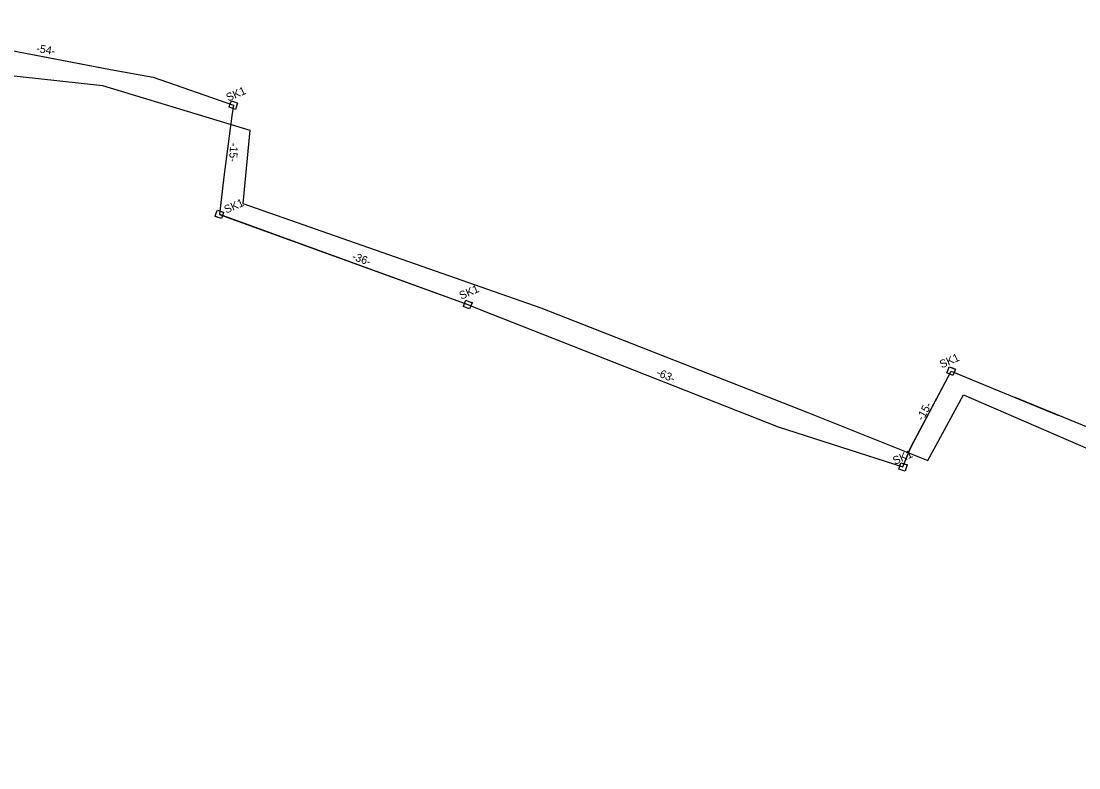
# Model space of a CAD drawing. Extents: x 6494530 to 6506885, y 5884901 to 5892312.
# Drawn here: x 6499332.9 to 6499475, y 5887627.2 to 5887727.6 of the extents above; entities that cross this region are included whole.
import ezdxf

# ---------------------------------------------------------------- set-up
doc = ezdxf.new("R2010")
doc.units = 0
for name, color, linetype in [('kabel W KANALIZACJI ISTN', 7, 'Continuous'), ('studnie do wyrysu', 7, 'Continuous'), ('trasa kanalizacji do wyrysu', 7, 'Continuous')]:
    doc.layers.add(name, color=color, linetype=linetype)

# ---------------------------------------------------------------- blocks, each defined once
blk = doc.blocks.new('ELARM2_27')
at = {"layer": 'studnie do wyrysu'}
blk.add_lwpolyline([(0, 0.45), (0.45, 0.45), (0.45, 0), (0.45, -0.45), (0, -0.45), (-0.45, -0.45), (-0.45, 0), (-0.45, 0.45)], close=True, dxfattribs=at)

msp = doc.modelspace()

# ---------------------------------------------------------------- linework, layer by layer
at = {"layer": 'kabel W KANALIZACJI ISTN'}
msp.add_lwpolyline([(6499307.31, 5887722.96), (6499343.79, 5887718.98), (6499363.61, 5887712.96), (6499362.68, 5887703.08), (6499402.72, 5887689.06), (6499438.59, 5887674.99), (6499454.69, 5887668.52), (6499459.49, 5887677.36), (6499509.73, 5887655.58), (6499508.58, 5887649.79), (6499539.76, 5887634.33), (6499552.17, 5887627.21)], dxfattribs=at)
at = {"layer": 'trasa kanalizacji do wyrysu'}
for points in [[(6499200, 5887702.73), (6499205.18, 5887704.15), (6499213.96, 5887706.58), (6499217.63, 5887707.07), (6499232.22, 5887710.84), (6499234.72, 5887711.24), (6499251.25, 5887715.34), (6499258.34, 5887717.61), (6499260.66, 5887718.13), (6499264.13, 5887717.94), (6499286.93, 5887723.59), (6499301.68, 5887727.63), (6499309.68, 5887726.99), (6499320.39, 5887725.83), (6499344.18, 5887721.25)], [(6499200, 5887702.73), (6499205.18, 5887704.15), (6499213.96, 5887706.58), (6499217.63, 5887707.07), (6499232.22, 5887710.84), (6499234.72, 5887711.24), (6499251.25, 5887715.34), (6499258.34, 5887717.61), (6499260.66, 5887718.13), (6499264.13, 5887717.94), (6499286.93, 5887723.59), (6499301.68, 5887727.63), (6499309.68, 5887726.99), (6499320.39, 5887725.83), (6499344.18, 5887721.25)], [(6499200, 5887702.73), (6499205.18, 5887704.14), (6499213.96, 5887706.57), (6499217.63, 5887707.06), (6499232.22, 5887710.83), (6499234.72, 5887711.23), (6499251.25, 5887715.33), (6499258.34, 5887717.6), (6499260.66, 5887718.12), (6499264.13, 5887717.93), (6499286.93, 5887723.58), (6499301.68, 5887727.62), (6499309.68, 5887726.98), (6499320.39, 5887725.82), (6499344.18, 5887721.25)], [(6499200, 5887702.73), (6499205.18, 5887704.14), (6499213.96, 5887706.57), (6499217.63, 5887707.06), (6499232.22, 5887710.83), (6499234.72, 5887711.23), (6499251.25, 5887715.33), (6499258.34, 5887717.6), (6499260.66, 5887718.12), (6499264.13, 5887717.93), (6499286.93, 5887723.58), (6499301.68, 5887727.62), (6499309.68, 5887726.98), (6499320.39, 5887725.82), (6499344.18, 5887721.25)], [(6499200, 5887702.73), (6499205.18, 5887704.14), (6499213.96, 5887706.57), (6499217.63, 5887707.06), (6499232.22, 5887710.83), (6499234.72, 5887711.23), (6499251.25, 5887715.33), (6499258.34, 5887717.6), (6499260.66, 5887718.12), (6499264.13, 5887717.93), (6499286.93, 5887723.58), (6499301.68, 5887727.62), (6499309.68, 5887726.98), (6499320.39, 5887725.82), (6499344.18, 5887721.25)], [(6499200, 5887702.73), (6499205.18, 5887704.14), (6499213.96, 5887706.57), (6499217.63, 5887707.06), (6499232.22, 5887710.83), (6499234.72, 5887711.23), (6499251.25, 5887715.33), (6499258.34, 5887717.6), (6499260.66, 5887718.12), (6499264.13, 5887717.93), (6499286.93, 5887723.58), (6499301.68, 5887727.62), (6499309.68, 5887726.98), (6499320.39, 5887725.82), (6499344.18, 5887721.25)], [(6499333.97, 5887723.22), (6499344.9, 5887721.12), (6499350.6, 5887720.08), (6499361.39, 5887716.34), (6499361.2, 5887714.9), (6499360.1, 5887706.68), (6499359.51, 5887701.65), (6499392.88, 5887689.51), (6499394.63, 5887688.81), (6499434.58, 5887673.09), (6499451.36, 5887667.68), (6499452.42, 5887670.32), (6499457.83, 5887680.57), (6499472.19, 5887674.66)], [(6499333.97, 5887723.22), (6499344.9, 5887721.12), (6499350.6, 5887720.08), (6499361.39, 5887716.34), (6499361.2, 5887714.9), (6499360.1, 5887706.68), (6499359.51, 5887701.65), (6499392.88, 5887689.51), (6499394.63, 5887688.81), (6499434.58, 5887673.09), (6499451.36, 5887667.68), (6499452.42, 5887670.32), (6499457.83, 5887680.57), (6499472.19, 5887674.66)], [(6499333.97, 5887723.22), (6499344.9, 5887721.12), (6499350.6, 5887720.08), (6499361.39, 5887716.34), (6499361.2, 5887714.9), (6499360.1, 5887706.68), (6499359.51, 5887701.65), (6499392.88, 5887689.51), (6499394.63, 5887688.81), (6499434.58, 5887673.09), (6499451.36, 5887667.68), (6499452.42, 5887670.32), (6499457.83, 5887680.57), (6499472.19, 5887674.66)], [(6499333.97, 5887723.22), (6499344.9, 5887721.12), (6499350.6, 5887720.08), (6499361.39, 5887716.34), (6499361.2, 5887714.9), (6499360.1, 5887706.68), (6499359.51, 5887701.65), (6499392.88, 5887689.51), (6499394.63, 5887688.81), (6499434.58, 5887673.09), (6499451.36, 5887667.68), (6499452.42, 5887670.32), (6499457.83, 5887680.57), (6499472.19, 5887674.66)], [(6499333.97, 5887723.21), (6499344.9, 5887721.11), (6499350.6, 5887720.07), (6499361.39, 5887716.33), (6499361.2, 5887714.89), (6499360.1, 5887706.67), (6499359.51, 5887701.64), (6499392.88, 5887689.5), (6499394.63, 5887688.8), (6499434.58, 5887673.08), (6499451.36, 5887667.67), (6499452.42, 5887670.31), (6499457.83, 5887680.56), (6499472.19, 5887674.65)], [(6499333.97, 5887723.21), (6499344.9, 5887721.11), (6499350.6, 5887720.07), (6499361.39, 5887716.33), (6499361.2, 5887714.89), (6499360.1, 5887706.67), (6499359.51, 5887701.64), (6499392.88, 5887689.5), (6499394.63, 5887688.8), (6499434.58, 5887673.08), (6499451.36, 5887667.67), (6499452.42, 5887670.31), (6499457.83, 5887680.56), (6499472.19, 5887674.65)], [(6499333.97, 5887723.21), (6499344.9, 5887721.11), (6499350.6, 5887720.07), (6499361.39, 5887716.33), (6499361.2, 5887714.89), (6499360.1, 5887706.67), (6499359.51, 5887701.64), (6499392.88, 5887689.5), (6499394.63, 5887688.8), (6499434.58, 5887673.08), (6499451.36, 5887667.67), (6499452.42, 5887670.31), (6499457.83, 5887680.56), (6499472.19, 5887674.65)], [(6499333.97, 5887723.21), (6499344.9, 5887721.11), (6499350.6, 5887720.07), (6499361.39, 5887716.33), (6499361.2, 5887714.89), (6499360.1, 5887706.67), (6499359.51, 5887701.64), (6499392.88, 5887689.5), (6499394.63, 5887688.8), (6499434.58, 5887673.08), (6499451.36, 5887667.67), (6499452.42, 5887670.31), (6499457.83, 5887680.56), (6499472.19, 5887674.65)], [(6499333.97, 5887723.21), (6499344.9, 5887721.11), (6499350.6, 5887720.07), (6499361.39, 5887716.33), (6499361.2, 5887714.89), (6499360.1, 5887706.67), (6499359.51, 5887701.64), (6499392.88, 5887689.5), (6499394.63, 5887688.8), (6499434.58, 5887673.08), (6499451.36, 5887667.67), (6499452.42, 5887670.31), (6499457.83, 5887680.56), (6499472.19, 5887674.65)], [(6499333.97, 5887723.21), (6499344.9, 5887721.11), (6499350.6, 5887720.07), (6499361.39, 5887716.33), (6499361.2, 5887714.89), (6499360.1, 5887706.67), (6499359.51, 5887701.64), (6499392.88, 5887689.5), (6499394.63, 5887688.8), (6499434.58, 5887673.08), (6499451.36, 5887667.67), (6499452.42, 5887670.31), (6499457.83, 5887680.56), (6499472.19, 5887674.65)], [(6499333.97, 5887723.21), (6499344.9, 5887721.11), (6499350.6, 5887720.07), (6499361.39, 5887716.33), (6499361.2, 5887714.89), (6499360.1, 5887706.67), (6499359.51, 5887701.64), (6499392.88, 5887689.5), (6499394.63, 5887688.8), (6499434.58, 5887673.08), (6499451.36, 5887667.67), (6499452.42, 5887670.31), (6499457.83, 5887680.56), (6499472.19, 5887674.65)], [(6499333.97, 5887723.21), (6499344.9, 5887721.11), (6499350.6, 5887720.07), (6499361.39, 5887716.33), (6499361.2, 5887714.89), (6499360.1, 5887706.67), (6499359.51, 5887701.64), (6499392.88, 5887689.5), (6499394.63, 5887688.8), (6499434.58, 5887673.08), (6499451.36, 5887667.67), (6499452.42, 5887670.31), (6499457.83, 5887680.56), (6499472.19, 5887674.65)], [(6499466.39, 5887677.04), (6499487.52, 5887668.35), (6499489.54, 5887665.93), (6499491.37, 5887665.2), (6499492.87, 5887665.38), (6499508.15, 5887658.35), (6499506.05, 5887650.18), (6499505.63, 5887649.07), (6499517.16, 5887642.63)], [(6499466.39, 5887677.04), (6499487.52, 5887668.34), (6499489.54, 5887665.92), (6499491.37, 5887665.19), (6499492.87, 5887665.37), (6499508.15, 5887658.34), (6499506.05, 5887650.17), (6499505.63, 5887649.06), (6499517.16, 5887642.62)], [(6499466.39, 5887677.04), (6499487.52, 5887668.34), (6499489.54, 5887665.92), (6499491.37, 5887665.19), (6499492.87, 5887665.37), (6499508.15, 5887658.34), (6499506.05, 5887650.17), (6499505.63, 5887649.06), (6499517.16, 5887642.62)], [(6499466.39, 5887677.04), (6499487.52, 5887668.34), (6499489.54, 5887665.92), (6499491.37, 5887665.19), (6499492.87, 5887665.37), (6499508.15, 5887658.34), (6499506.05, 5887650.17), (6499505.63, 5887649.06), (6499517.16, 5887642.62)], [(6499466.39, 5887677.04), (6499487.52, 5887668.34), (6499489.54, 5887665.92), (6499491.37, 5887665.19), (6499492.87, 5887665.37), (6499508.15, 5887658.34), (6499506.05, 5887650.17), (6499505.63, 5887649.06), (6499517.16, 5887642.62)], [(6499466.39, 5887677.04), (6499487.52, 5887668.35), (6499489.54, 5887665.93), (6499491.37, 5887665.2), (6499492.87, 5887665.38), (6499508.15, 5887658.35), (6499506.05, 5887650.18), (6499505.63, 5887649.07), (6499517.16, 5887642.63)]]:
    msp.add_lwpolyline(points, dxfattribs=at)

# ---------------------------------------------------------------- block references
at = {"layer": 'studnie do wyrysu'}
for p, rotation in [((6499361.39, 5887716.33), -20.10942046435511), ((6499361.39, 5887716.33), -20.10942046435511), ((6499361.39, 5887716.33), -20.10942046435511), ((6499361.39, 5887716.33), -20.10942046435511), ((6499361.39, 5887716.33), -20.10942046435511), ((6499361.39, 5887716.33), -20.10942046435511), ((6499359.51, 5887701.65), 160.10667272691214), ((6499359.51, 5887701.64), 160.10667272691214), ((6499359.51, 5887701.64), 160.10667272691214), ((6499359.51, 5887701.64), 160.10667272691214), ((6499359.51, 5887701.64), 160.10667272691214), ((6499359.51, 5887701.65), 160.10667272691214), ((6499392.88, 5887689.51), -21.240071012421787), ((6499392.88, 5887689.51), -21.240071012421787), ((6499392.88, 5887689.5), -21.240071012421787), ((6499392.88, 5887689.5), -21.240071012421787), ((6499392.88, 5887689.5), -21.240071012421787), ((6499392.88, 5887689.5), -21.240071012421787), ((6499457.83, 5887680.57), -22.59255526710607), ((6499457.83, 5887680.56), -22.59255526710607), ((6499457.83, 5887680.56), -22.59255526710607), ((6499457.83, 5887680.56), -22.59255526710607), ((6499457.83, 5887680.56), -22.59255526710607), ((6499457.83, 5887680.57), -22.59255526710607), ((6499451.36, 5887667.68), -16.755748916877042), ((6499451.36, 5887667.68), -16.755748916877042), ((6499451.36, 5887667.67), -16.755748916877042), ((6499451.36, 5887667.67), -16.755748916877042), ((6499451.36, 5887667.67), -16.755748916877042), ((6499451.36, 5887667.67), -16.755748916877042)]:
    msp.add_blockref('ELARM2_27', p, dxfattribs=dict(at, rotation=rotation))

# ---------------------------------------------------------------- texts
for p in [(6499360.7, 5887716.8), (6499360.7, 5887716.8), (6499360.43, 5887701.73), (6499360.43, 5887701.73), (6499392.02, 5887690.16), (6499392.02, 5887690.16), (6499456.57, 5887680.92), (6499456.57, 5887680.92), (6499450.28, 5887667.95), (6499450.28, 5887667.95)]:
    msp.add_text('SK1', height=1.075, rotation=23.6947, dxfattribs=at).set_placement(p)
at = {"layer": 'trasa kanalizacji do wyrysu'}
for s, rotation, p in [('-54-', 349.9142, (6499334.85, 5887723.49)), ('-54-', 349.9142, (6499334.85, 5887723.49)), ('-15-', 266.8348, (6499360.96, 5887711.28)), ('-15-', 266.8348, (6499360.96, 5887711.28)), ('-36-', 340.2826, (6499377.24, 5887695.58)), ('-36-', 340.2826, (6499377.24, 5887695.58)), ('-63-', 337.0234, (6499418.12, 5887680)), ('-63-', 337.0234, (6499418.12, 5887680)), ('-15-', 61.2374, (6499454.05, 5887673.78)), ('-15-', 61.2374, (6499454.05, 5887673.78))]:
    msp.add_text(s, height=1.075, rotation=rotation, dxfattribs=at).set_placement(p)

doc.saveas('drawing.dxf')
